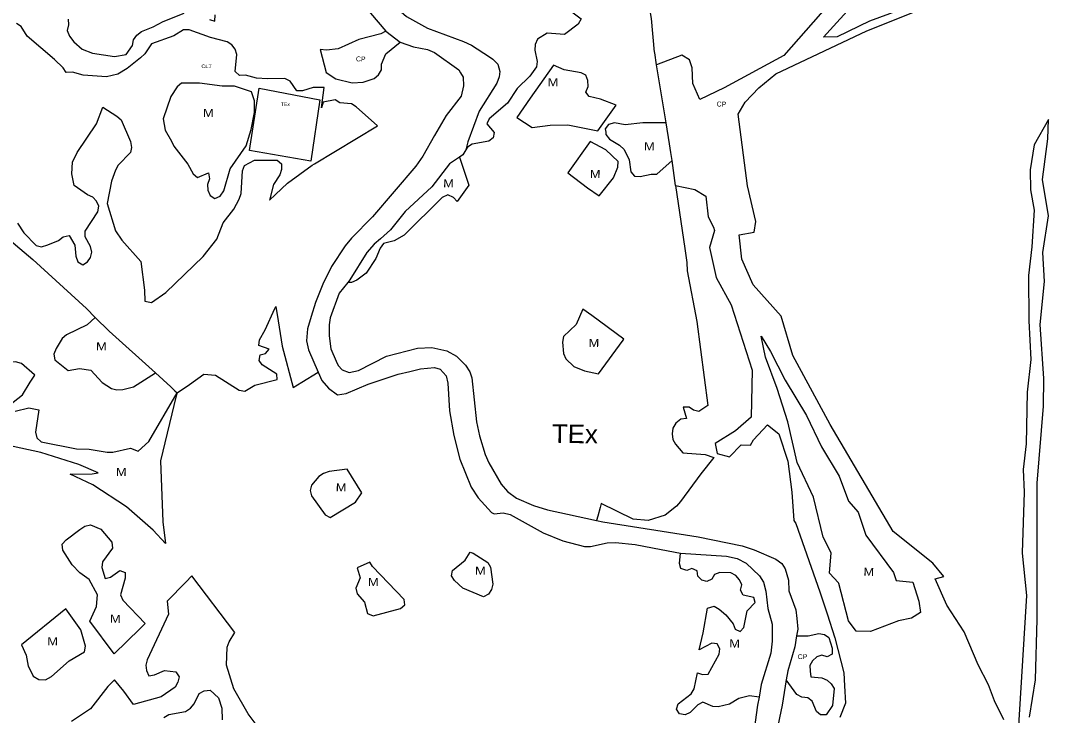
# Model space of a CAD drawing. Extents: x 713589 to 726391, y 7177764 to 7191819.
# Drawn here: x 717458 to 718794, y 7180202 to 7181104 of the extents above; entities that cross this region are included whole.
import ezdxf
from ezdxf.enums import TextEntityAlignment as Align

# ---------------------------------------------------------------- set-up
doc = ezdxf.new("R2010")
doc.units = 0
doc.header["$LTSCALE"] = 2.6
doc.layers.add('63', color=7, linetype='Continuous', lineweight=25)

msp = doc.modelspace()

# ---------------------------------------------------------------- linework, layer by layer
at = {"layer": '63'}
for p, q in [((717932.94, 7181090.31), (717951.45, 7181076.06)), ((718297.19, 7180971.48), (718284.8, 7181046.78)), ((718309.5, 7180890.28), (718304.79, 7180922.77))]:
    msp.add_line(p, q, dxfattribs=at)
for points in [[(717975.51, 7181305.21), (717968.19, 7181295.97), (717951.58, 7181282.26), (717926.69, 7181264.78), (717912.02, 7181249.6), (717905.6, 7181239.24), (717896.88, 7181208.26), (717896.73, 7181192.35), (717901.18, 7181177.19), (717910.76, 7181162.32), (717935.07, 7181131.68), (717959.73, 7181109.56), (717987.25, 7181094.37), (718033.83, 7181076.88), (718044.38, 7181072.47), (718067.72, 7181057.05), (718072.15, 7181054.12), (718078.47, 7181047.53), (718081.11, 7181038.35), (718080.28, 7181031.2), (718077.14, 7181023.14), (718054.19, 7180986.8), (718039.34, 7180946.76), (718036.99, 7180936.65)], [(718284.8, 7181046.78), (718282.27, 7181062.19), (718282.17, 7181063.2), (718278.04, 7181106.99), (718270.15, 7181153.06), (718266.4, 7181200.41)], [(717890.61, 7181140.52), (717932.94, 7181090.31)], [(718526.07, 7181145.73), (718450.04, 7181058.87), (718372.71, 7181016.76), (718340.78, 7181001.63), (718331.9, 7181022.36), (718330.92, 7181042.76), (718327.3, 7181053.3), (718317.43, 7181059.55), (718284.8, 7181046.78)], [(718600.11, 7181117.75), (718561.28, 7181103.6), (718519.48, 7181083.21), (718501.71, 7181082.88), (718545.49, 7181130.59)], [(717520.19, 7181106.21), (717520.84, 7181098.64), (717519.2, 7181091.4), (717522.16, 7181083.83), (717527.75, 7181076.59), (717538.61, 7181067.04), (717552.1, 7181061.78), (717580.73, 7181057.49), (717595.54, 7181060.12), (717603.77, 7181071.97), (717605.41, 7181079.21), (717609.36, 7181085.46), (717615.62, 7181090.06), (717630.75, 7181095.98), (717643.59, 7181103.22), (717670.9, 7181113.75)], [(717703.81, 7181105.51), (717710.72, 7181103.54), (717711.38, 7181111.77)], [(718171.33, 7181122.3), (718174.6, 7181115.78), (718186.78, 7181106.57), (718182.83, 7181099.66), (718165.05, 7181086.17), (718142.68, 7181087.82), (718130.17, 7181080.25), (718127.21, 7181073.34), (718126.55, 7181065.77), (718129.51, 7181051.29), (718128.85, 7181044.05), (718119.96, 7181031.88), (718103.5, 7181016.09), (718091, 7180997), (718067.3, 7180976.6), (718064.01, 7180970.02), (718073.88, 7180958.83), (718072.23, 7180951.92), (718066.64, 7180947.65), (718045.25, 7180943.7), (718038.99, 7180940.08), (718036.99, 7180936.65)], [(718735.81, 7180196.62), (718723.68, 7180221.01), (718716.12, 7180242.07), (718702.63, 7180267.74), (718684.21, 7180310.85), (718661.84, 7180345.08), (718646.42, 7180379.46), (718657.76, 7180382.5), (718643.42, 7180399.71), (718592.09, 7180440.85), (718510.18, 7180579.73), (718461.82, 7180669.25), (718446.69, 7180720.58), (718410.17, 7180761.07), (718395.37, 7180794.63), (718392.09, 7180826.23), (718411.5, 7180829.51), (718413.48, 7180843.33), (718402.96, 7180889.73), (718390.8, 7180982.86), (718399.69, 7180998.33), (718417.46, 7181017.08), (718439.51, 7181035.18), (718557.66, 7181090.77), (718617.55, 7181114.78)], [(717539.92, 7181033.48), (717526.1, 7181037.1), (717517.87, 7181036.77), (717513.92, 7181042.7), (717502.41, 7181053.89), (717467.2, 7181083.84), (717459.31, 7181096.67), (717453.39, 7181100.62)], [(717462.88, 7180828.48), (717478.67, 7180812.35), (717485.91, 7180810.71), (717493.81, 7180813.01), (717507.63, 7180818.6), (717513.89, 7180823.53), (717521.45, 7180825.18), (717529.02, 7180812.67), (717530.33, 7180798.19), (717532.97, 7180790.95), (717539.55, 7180787), (717545.47, 7180790.95), (717549.42, 7180796.87), (717551.07, 7180803.78), (717549.42, 7180811.02), (717542.51, 7180823.53), (717542.52, 7180830.77), (717558.97, 7180856.1), (717559.96, 7180863.34), (717557.33, 7180869.93), (717552.4, 7180875.19), (717545.49, 7180878.16), (717528.05, 7180890.33), (717525.09, 7180905.14), (717525.75, 7180920.28), (717532, 7180933.11), (717557.35, 7180970.29), (717565.25, 7180992.01), (717583.35, 7180980.16), (717589.27, 7180975.22), (717601.11, 7180947.25), (717602.76, 7180939.68), (717601.11, 7180932.77), (717585.31, 7180916.32), (717581.69, 7180910.07), (717576.42, 7180895.59), (717570.82, 7180866.96), (717582, 7180831.42), (717590.23, 7180819.24), (717614.58, 7180791.27), (717619.51, 7180754.41), (717619.83, 7180739.93), (717628.39, 7180738.29), (717647.15, 7180751.12), (717695.53, 7180797.84), (717713.3, 7180820.54), (717721.86, 7180841.6), (717735.36, 7180859.36), (717742.6, 7180872.53), (717744.9, 7180879.77), (717746.88, 7180909.38), (717749.52, 7180915.96), (717762.35, 7180923.2), (717791.97, 7180923.19), (717797.56, 7180918.26), (717797.56, 7180911.02), (717795.25, 7180903.78), (717787.03, 7180891.28), (717781.76, 7180871.2), (717805.45, 7180893.25), (717837.38, 7180916.6), (717840.45, 7180918.45), (717922.16, 7180967.72), (717894.65, 7180992.28), (717888.4, 7180996.23), (717873.26, 7180997.55), (717867.34, 7181001.5), (717851.54, 7180998.21), (717849.65, 7180990.81), (717853.05, 7181017.48), (717838.71, 7181017.3), (717824.56, 7181013.02), (717817.32, 7181013.03), (717808.77, 7181025.53), (717801.86, 7181029.15), (717779.48, 7181028.5), (717765, 7181029.49), (717750.52, 7181033.44), (717742.96, 7181033.11), (717737.36, 7181038.05), (717739.34, 7181060.1), (717737.37, 7181067.34), (717733.09, 7181072.93), (717726.84, 7181076.55), (717705.12, 7181082.15), (717677.48, 7181092.03), (717670.24, 7181092.03), (717657.41, 7181084.46), (717628.78, 7181073.94), (717619.89, 7181061.11), (717614.29, 7181055.84), (717596.85, 7181042.02), (717584.67, 7181034.79), (717570.19, 7181031.17), (717539.92, 7181033.48)], [(717932.94, 7181090.31), (717926.59, 7181087.05), (717897.96, 7181079.81), (717870.97, 7181067.64), (717855.83, 7181065.67), (717847.84, 7181066.72), (717855.53, 7181036.99), (717868, 7181028.81), (717889.39, 7181023.54), (717903.54, 7181024.2), (717917.69, 7181029.13), (717923.29, 7181033.74), (717927.24, 7181040.32), (717927.24, 7181047.56), (717932.83, 7181061.05), (717951.45, 7181076.06)], [(717951.45, 7181076.06), (717968.79, 7181069.97), (717987.3, 7181066.57), (717996.39, 7181062.82), (718027.75, 7181040.48), (718030.13, 7181036.45), (718033.48, 7181030.78), (718033.95, 7181019.44), (718030.76, 7181005.99), (718011.29, 7180981.19), (717996.42, 7180955.23), (717981.2, 7180928.22), (717972.12, 7180915.44), (717915.68, 7180849.6), (717888.61, 7180821.73), (717880.26, 7180811.89), (717862.62, 7180784.98), (717851.28, 7180762.04), (717841.73, 7180738.09), (717836.18, 7180720), (717831.31, 7180704.15), (717830.16, 7180688.3), (717832.63, 7180676.81), (717845.15, 7180647.79)], [(718297.19, 7180971.48), (718267.04, 7180971.3), (718244.01, 7180968.68), (718229.86, 7180971.31), (718222.29, 7180969.34), (718218.01, 7180963.74), (718218.62, 7180959.26), (718219, 7180956.5), (718223.6, 7180950.25), (718236.77, 7180942.35), (718242.69, 7180936.76), (718249.27, 7180923.59), (718251.24, 7180907.8), (718255.84, 7180902.2), (718263.41, 7180901.87), (718277.89, 7180904.83), (718285.13, 7180904.83), (718304.79, 7180922.77)], [(718304.79, 7180922.77), (718303.31, 7180933.11), (718301.7, 7180944.09), (718297.19, 7180971.48)], [(718788.5, 7180765.41), (718786.53, 7180803.25), (718793.78, 7180850.64), (718786.22, 7180898.03), (718793.14, 7180950.68), (718793.75, 7180975.61), (718775.04, 7180942.78), (718770.09, 7180910.53), (718770.42, 7180884.54), (718775.02, 7180858.21), (718772.38, 7180810.5), (718767.77, 7180773.31), (718768.41, 7180714.41), (718771.04, 7180664.06), (718766.09, 7180621.61), (718764.77, 7180554.81), (718761.14, 7180521.57), (718762.12, 7180491.96), (718759.82, 7180413.44), (718759.81, 7180412.98), (718765.06, 7180358.02), (718753.62, 7180167.91)], [(718036.99, 7180936.65), (718033.14, 7180929.96), (718028.78, 7180927.07)], [(718028.78, 7180927.07), (718029.74, 7180924.17), (718040.9, 7180890.42), (718025.47, 7180869.45), (718020.88, 7180874.6), (718013.64, 7180877.89), (718006.4, 7180874.6), (717956.71, 7180825.58), (717943.87, 7180818.34), (717930.05, 7180814.73), (717925.44, 7180808.8), (717919.84, 7180795.31), (717907.34, 7180776.23), (717895.16, 7180767.35), (717888.25, 7180764.39), (717883.49, 7180764.34)], [(718028.78, 7180927.07), (718015.63, 7180918.38), (717992.77, 7180888.31), (717958.24, 7180856.36), (717938.99, 7180832.49), (717926.18, 7180820.78), (717917.72, 7180813.83), (717908.47, 7180803.06), (717886.2, 7180767.77), (717883.49, 7180764.34)], [(718309.5, 7180890.28), (718321.38, 7180808.49), (718324.05, 7180790.09), (718324.53, 7180779.41), (718337.2, 7180713.41), (718351.43, 7180604.53), (718339.72, 7180596.87), (718332.81, 7180598.52), (718326.89, 7180602.47), (718319.32, 7180602.14), (718323.6, 7180587.66), (718316.36, 7180586.68), (718309.78, 7180581.74), (718305.83, 7180575.16), (718304.84, 7180567.59), (718305.82, 7180560.35), (718309.11, 7180554.1), (718318.65, 7180543.24), (718347.94, 7180540.93), (718359.13, 7180536.92), (718342.1, 7180515.97), (718315.7, 7180479.81), (718310.5, 7180473.85), (718296.02, 7180462.34), (718273.65, 7180455.43), (718254.23, 7180456.75), (718212.81, 7180477.47), (718211.46, 7180472.24), (718208.49, 7180460.71), (718206.73, 7180455.32)], [(718309.5, 7180890.28), (718334.51, 7180884.81), (718348.66, 7180876.25), (718351.94, 7180849.27), (718358.78, 7180835.87), (718359.78, 7180831.77), (718353.58, 7180809.78), (718362.13, 7180770.62), (718381.54, 7180735.4), (718408.84, 7180650.5), (718407.51, 7180589.29), (718387.44, 7180571.53), (718361.01, 7180555.13), (718363.5, 7180542.29), (718379.35, 7180537.66), (718394.67, 7180553.43), (718406.52, 7180553.09), (718410.8, 7180560), (718428.9, 7180579.42), (718443.38, 7180567.9), (718455.22, 7180532.35), (718460.47, 7180491.88), (718463.15, 7180455.39), (718465.73, 7180451.4), (718496.6, 7180362.73), (718506.52, 7180334.24), (718516.38, 7180302.98), (718527.89, 7180257.57), (718528.87, 7180240.76), (718530.19, 7180218.08), (718522.62, 7180199.65)], [(717431.49, 7180829.8), (717474.59, 7180794.25), (717544.01, 7180730.4), (717555.57, 7180718.96)], [(717454.33, 7180841.32), (717462.88, 7180828.48)], [(717883.49, 7180764.34), (717872.51, 7180750.43), (717860.82, 7180718.26), (717859.23, 7180709.27), (717859.59, 7180694.87), (717861.62, 7180678.14), (717868.67, 7180661.99), (717871.04, 7180656.56), (717876.36, 7180650.69), (717885.32, 7180647.18), (717897.49, 7180649.75), (717933.99, 7180668.55), (717974.1, 7180678.91), (717992.98, 7180679.69), (718012.4, 7180675.35), (718024.74, 7180668.76), (718036.55, 7180657.03), (718042.01, 7180648.36), (718044.77, 7180640.52), (718050.69, 7180583.16), (718054.85, 7180565.16), (718061.99, 7180541.01), (718066.84, 7180529.99), (718082.68, 7180502.17), (718091.01, 7180493.06), (718102.88, 7180484.41), (718124.73, 7180474.54), (718142.9, 7180468.88), (718169.17, 7180463.61), (718206.73, 7180455.32)], [(718769.31, 7180199.74), (718776.89, 7180248.44), (718779.21, 7180327.09), (718779.23, 7180425.23), (718779.24, 7180503.8), (718787.48, 7180603.84), (718787.82, 7180639.7), (718783.22, 7180709.8), (718788.5, 7180765.41)], [(717661.8, 7180620.76), (717678.12, 7180631.59), (717696.55, 7180645.08), (717711.69, 7180643.76), (717742.62, 7180624.34), (717749.86, 7180623.02), (717762.69, 7180630.92), (717791.98, 7180638.15), (717791.33, 7180645.39), (717772.57, 7180657.24), (717768.29, 7180662.84), (717769.94, 7180670.08), (717776.85, 7180672.05), (717781.46, 7180677.64), (717767.97, 7180682.58), (717768.96, 7180689.82), (717776.2, 7180702.65), (717788.95, 7180730.25), (717790.22, 7180733), (717790.47, 7180730.52), (717793.27, 7180714.32), (717798.24, 7180681.59), (717812.43, 7180628.05), (717823.97, 7180635.01), (717845.15, 7180647.79)], [(717555.57, 7180718.96), (717545.13, 7180709.14), (717518.14, 7180696.32), (717512.55, 7180691.38), (717504.65, 7180678.55), (717501.68, 7180670.98), (717503, 7180663.74), (717520.48, 7180649.97), (717535.14, 7180652.59), (717549.69, 7180650.34), (717564.6, 7180634.32), (717576.6, 7180626.63), (717583.43, 7180624.94), (717591.17, 7180625.33), (717605.42, 7180628.7), (717633.69, 7180646.71)], [(717555.57, 7180718.96), (717573.62, 7180701.11), (717633.69, 7180646.71)], [(717633.69, 7180646.71), (717653.57, 7180628.7), (717658.9, 7180623.56), (717661.8, 7180620.76)], [(717845.15, 7180647.79), (717849.74, 7180637.14), (717858.46, 7180626.9), (717870.09, 7180618.55), (717881.31, 7180620.09), (717909.94, 7180632.13), (717949.1, 7180645.35), (717964.21, 7180648.68), (717977.9, 7180652.23), (717996.39, 7180654.03), (718003.47, 7180651.73), (718011.42, 7180643.01), (718013.75, 7180633.58), (718015.82, 7180597.41), (718021.23, 7180565.4), (718029.23, 7180534.69), (718043.7, 7180498.44), (718053.08, 7180484.8), (718070.46, 7180465.6), (718073.91, 7180463.98), (718085.23, 7180465.2), (718094.63, 7180463.17), (718137.31, 7180439.19), (718163.03, 7180428.9), (718191.02, 7180421.54), (718195.73, 7180421.5), (718198.88, 7180421.47), (718220.41, 7180426.05), (718231.16, 7180426.58), (718256.82, 7180423.98), (718290.54, 7180417.73), (718315.94, 7180412.89)], [(717451.39, 7180597.08), (717469.16, 7180601.68), (717482.19, 7180599.05), (717478.04, 7180569.76), (717479.68, 7180562.52), (717485.28, 7180557.26), (717531.34, 7180548.36), (717547.47, 7180548.03), (717571.16, 7180543.75), (717578.4, 7180543.75), (717601.11, 7180549.01), (717611.17, 7180545.26), (717625.06, 7180557.96), (717661.8, 7180620.76), (717660.61, 7180617.18), (717640.2, 7180532.61), (717643.15, 7180453.64), (717646.75, 7180425.54), (717630.97, 7180442.78), (717596.09, 7180473.06), (717552.33, 7180501.37), (717522.78, 7180515.24), (717551.35, 7180515.85), (717559.35, 7180517.29), (717534.02, 7180527.91), (717484.66, 7180543.71), (717432.67, 7180554.91)], [(718206.73, 7180455.32), (718214.82, 7180453.53), (718338.71, 7180433.94), (718395.82, 7180422.23), (718411.51, 7180417.25), (718439.72, 7180405.03), (718447.34, 7180399.35), (718451.65, 7180392.37), (718456.2, 7180377.79), (718456.62, 7180363.96), (718465.77, 7180339.2), (718466.83, 7180328.17)], [(718417.78, 7180225.72), (718405.38, 7180227.39), (718391.76, 7180224.09), (718379.46, 7180216.82), (718364.78, 7180213.25), (718357.77, 7180213.65), (718344.81, 7180219.47), (718338.46, 7180216.03), (718328.54, 7180205.98), (718321.66, 7180203.07), (718314.52, 7180204.4), (718310.55, 7180210.22), (718312.8, 7180217.22), (718329.86, 7180230.18), (718333.57, 7180236.66), (718337.8, 7180257.56), (718344.55, 7180255.17), (718351.82, 7180255.7), (718366.11, 7180281.49), (718367.04, 7180288.63), (718363.6, 7180295.11), (718356.46, 7180295.77), (718339.97, 7180287.5), (718345.45, 7180309.4), (718350.73, 7180341.6), (718359.59, 7180343.83), (718366.22, 7180340.16), (718374.79, 7180332.59), (718384.31, 7180320.95), (718386.69, 7180314.07), (718393.31, 7180311.29), (718398.07, 7180316.45), (718402.44, 7180337.87), (718412.89, 7180348.72), (718411.17, 7180355.46), (718397.15, 7180358.37), (718393.71, 7180364.59), (718395.56, 7180371.6), (718392.52, 7180378.08), (718387.76, 7180383.9), (718381.36, 7180387.18), (718366.97, 7180387.66), (718360.04, 7180385.31), (718356.6, 7180379.22), (718350.12, 7180375.92), (718343.38, 7180377.9), (718338.22, 7180382.8), (718337.3, 7180389.94), (718330.69, 7180392.72), (718323.81, 7180390.34), (718316.4, 7180392.85), (718314.42, 7180399.47), (718315.94, 7180412.89)], [(718315.94, 7180412.89), (718375.59, 7180408.9), (718389.43, 7180406.08), (718400.89, 7180399.61), (718418.52, 7180383.35), (718423.46, 7180375.05), (718426.7, 7180363.41), (718429.43, 7180341.05), (718435.04, 7180320.51), (718435.01, 7180298.64), (718433.02, 7180283.01), (718420.63, 7180242.17), (718417.78, 7180225.72)], [(717763.42, 7180192), (717754.23, 7180204.14), (717735.53, 7180236.63), (717726.02, 7180267.48), (717727.01, 7180290.78), (717729.31, 7180297.68), (717736.86, 7180309.62), (717681.19, 7180383.43), (717673.17, 7180375.13), (717648.95, 7180350.45), (717650.55, 7180333.79), (717622.97, 7180274.39), (717621.33, 7180267.5), (717621.98, 7180260.28), (717625.26, 7180253.72), (717632.48, 7180254.7), (717645.61, 7180260.61), (717660.38, 7180258.63), (717664.32, 7180252.4), (717662.67, 7180245.18), (717659.39, 7180238.94), (717641.01, 7180226.48), (717605.05, 7180216.49), (717592.52, 7180233.84), (717580.44, 7180248.56), (717571.77, 7180239.62), (717549.45, 7180210.74), (717524.83, 7180194.33)], [(718466.83, 7180328.17), (718468.17, 7180314.29), (718466.66, 7180305.49)], [(718466.66, 7180305.49), (718481.5, 7180305.42), (718495.65, 7180308.38), (718502.89, 7180307.39), (718508.49, 7180303.11), (718512.76, 7180289.29), (718512.76, 7180281.72), (718506.51, 7180278.11), (718499.6, 7180280.41), (718492.69, 7180278.11), (718487.42, 7180273.17), (718483.8, 7180266.92), (718484.13, 7180259.68), (718485.11, 7180252.44), (718499.59, 7180250.79), (718506.17, 7180247.83), (718511.44, 7180243.22), (718515.38, 7180236.97), (718513.41, 7180215.25), (718505.18, 7180203.08), (718497.61, 7180202.75), (718492.34, 7180207.36), (718486.75, 7180220.52), (718481.16, 7180225.13), (718473.26, 7180225.79), (718467.01, 7180229.41), (718453.27, 7180248.52)], [(718466.66, 7180305.49), (718464.19, 7180291.05), (718455.25, 7180260.24), (718453.27, 7180248.52)], [(718453.27, 7180248.52), (718447.7, 7180215.62), (718440.47, 7180180.39)], [(717644.62, 7180199.56), (717651.18, 7180203.17), (717672.84, 7180207.11), (717679.08, 7180211.37), (717684, 7180217.28), (717690.57, 7180230.41), (717696.8, 7180234.01), (717704.68, 7180235), (717715.51, 7180224.82), (717719.77, 7180211.37), (717720.43, 7180196.6)], [(718417.78, 7180225.72), (718416.02, 7180215.6), (718411.5, 7180183.76), (718414.1, 7180158.63), (718430.81, 7180094.32), (718451.52, 7180039.92), (718460.36, 7180018.74), (718474.48, 7179994.61), (718481.19, 7179977.94), (718482.95, 7179964.54), (718477.85, 7179941.62), (718478, 7179926.8), (718483.38, 7179909.83), (718495.38, 7179892.46), (718501.65, 7179886), (718510.02, 7179881), (718546.1, 7179876.34), (718573.47, 7179863.35)]]:
    msp.add_lwpolyline(points, dxfattribs=at)
for points in [[(718193.01, 7181011.46), (718195.64, 7181018.7), (718195.32, 7181026.27), (718193.01, 7181033.18), (718186.76, 7181036.47), (718164.72, 7181040.1), (718150.86, 7181046.16), (718120.39, 7181003.69), (718102.98, 7180978.4), (718122.91, 7180965.41), (718146.28, 7180968.36), (718169.31, 7180968.69), (718208.3, 7180961.23), (718232.06, 7180994.61), (718211.77, 7181002.25), (718197.29, 7181005.87)], [(717736.37, 7181019.29), (717720.25, 7181018.97), (717690.96, 7181022.92), (717667.6, 7181022.92), (717662, 7181018.32), (717653.77, 7181005.49), (717643.9, 7180976.86), (717646.53, 7180962.05), (717654.7, 7180947.49), (717657.71, 7180940.99), (717675.8, 7180917.95), (717682.71, 7180905.11), (717688.31, 7180900.51), (717702.46, 7180906.43), (717703.77, 7180898.86), (717701.47, 7180891.62), (717701.8, 7180884.05), (717704.76, 7180877.14), (717711.01, 7180873.19), (717717.92, 7180876.48), (717722.53, 7180883.06), (717730.76, 7180911.69), (717751.5, 7180941.63), (717758.08, 7180963.02), (717762.36, 7180985.06), (717762.36, 7180999.87), (717758.42, 7181011.72)], [(717835.4, 7180921.54), (717755.77, 7180935.38), (717768.62, 7181016.33), (717847.45, 7181001.21)], [(718198.29, 7180947.17), (718169.53, 7180906.77), (718195.07, 7180887.18), (718210.07, 7180876.78), (718228.86, 7180899.9), (718234.46, 7180913.72), (718234.79, 7180921.29), (718218.67, 7180936.43)], [(718177.15, 7180655.08), (718190.97, 7180649.49), (718209.24, 7180645.48), (718241.11, 7180689.4), (718241.98, 7180690.7), (718200.64, 7180721.33), (718189.06, 7180729.51), (718180.12, 7180709.71), (718163.67, 7180693.92), (718162.35, 7180686.68), (718163.99, 7180671.87), (718166.95, 7180664.96)], [(718455.23, 7180583.36), (718441.41, 7180626.8), (718426.28, 7180667.28), (718420.69, 7180694.59), (718432.87, 7180674.52), (718451.94, 7180637.33), (718479.58, 7180591.58), (718498.99, 7180550.77), (718522.01, 7180512.6), (718534.18, 7180480.35), (718546.69, 7180465.87), (718556.55, 7180436.25), (718592.41, 7180387.87), (718595.84, 7180377.2), (718617.55, 7180375.05), (718625.31, 7180350.68), (718627.62, 7180335.87), (718615.77, 7180328.63), (718598.98, 7180325.01), (718562.78, 7180311.2), (718544.03, 7180311.53), (718534.16, 7180325.03), (718521.3, 7180373.25), (718521, 7180374.39), (718509.16, 7180386.9), (718511.47, 7180413.22), (718501.27, 7180433.63), (718488.77, 7180485.62), (718467.39, 7180530.71)], [(717405.59, 7180638.75), (717417.95, 7180626.64), (717421.38, 7180623.28), (717429.93, 7180602.22), (717436.84, 7180599.25), (717460.87, 7180618.34), (717471.07, 7180634.65), (717476.92, 7180644.01), (717476.67, 7180644.33), (717459.56, 7180659.14), (717451.99, 7180661.12), (717444.42, 7180660.79), (717414.15, 7180656.85), (717407.9, 7180653.23), (717404.93, 7180645.99)], [(717836.56, 7180487.38), (717854.32, 7180462.7), (717860.9, 7180459.08), (717893.48, 7180478.81), (717901.64, 7180491.08), (717882.65, 7180521.85), (717859.6, 7180518.64), (717852.03, 7180516.34), (717845.77, 7180512.39), (717836.23, 7180501.2), (717834.58, 7180494.29)], [(717577.74, 7180419.37), (717564.91, 7180401.61), (717564.25, 7180394.04), (717568.52, 7180379.89), (717575.43, 7180381.53), (717587.28, 7180390.09), (717594.19, 7180387.78), (717594.52, 7180380.54), (717588.26, 7180358.82), (717591.22, 7180351.58), (717620.41, 7180321.36), (717613.57, 7180314.38), (717580.1, 7180282.25), (717548.49, 7180324.61), (717557, 7180343.69), (717558.65, 7180358.5), (717547.46, 7180378.57), (717535.62, 7180387.13), (717525.42, 7180397.66), (717513.57, 7180416.75), (717512.59, 7180424.32), (717517.85, 7180430.24), (717535.63, 7180443.4), (717541.88, 7180447.68), (717549.45, 7180449.65), (717562.61, 7180444.06), (717577.09, 7180426.94)], [(718059.97, 7180356.04), (718032.99, 7180367.24), (718022.13, 7180377.11), (718018.18, 7180383.36), (718019.5, 7180390.27), (718035.96, 7180403.76), (718042.52, 7180413.97), (718046.49, 7180412.64), (718065.57, 7180400.79), (718068.86, 7180394.54), (718071.82, 7180372.49), (718070.17, 7180365.58), (718066.22, 7180359.66)], [(717916.49, 7180331.39), (717952.03, 7180340.92), (717957.63, 7180345.53), (717956.64, 7180352.77), (717915.52, 7180395.56), (717912.37, 7180401.28), (717895.73, 7180393.78), (717899.72, 7180380.75), (717894.12, 7180367.26), (717895.77, 7180360.02), (717905.31, 7180349.16), (717909.25, 7180334.35)], [(717498.74, 7180252.55), (717521.77, 7180272.95), (717541.52, 7180284.79), (717542.84, 7180292.03), (717536.92, 7180313.09), (717517.38, 7180340.69), (717459.83, 7180293.67), (717465.83, 7180280.2), (717468.46, 7180266.05), (717471.75, 7180259.46), (717475.04, 7180253.21), (717482.28, 7180248.93), (717490.84, 7180248.27)]]:
    msp.add_lwpolyline(points, close=True, dxfattribs=at)

# ---------------------------------------------------------------- texts
for s, height, width, p in [('CP', 6.4, 1.05, (717900.39, 7181051.21)), ('CLT', 4.64, 1.15, (717700.12, 7181042.54)), ('M', 10.4, 1.2, (718150.12, 7181018.99)), ('M', 10.4, 1.2, (717702.38, 7180979.06)), ('TEx', 4.8, 1.05, (717802.4, 7180993.37)), ('CP', 6.4, 1.05, (718369.02, 7180992.65)), ('M', 10.4, 1.2, (718275.23, 7180935.86)), ('M', 10.4, 1.2, (718204.92, 7180899.94)), ('M', 10.4, 1.2, (718014.31, 7180887.82)), ('M', 10.4, 1.2, (717563.43, 7180676.18)), ('M', 10.4, 1.2, (718203.24, 7180680.52)), ('TEx', 24, 1.05, (718178.45, 7180555.71)), ('M', 10.4, 1.2, (717589.26, 7180513.02)), ('M', 10.4, 1.2, (717874.83, 7180492.96)), ('M', 10.4, 1.2, (718055.76, 7180384.91)), ('M', 10.4, 1.2, (718560.36, 7180383.42)), ('M', 10.4, 1.2, (717916.7, 7180370.08)), ('M', 10.4, 1.2, (717581.56, 7180322.39)), ('M', 10.4, 1.2, (717500.08, 7180293.17)), ('M', 10.4, 1.2, (718386.02, 7180290.29)), ('CP', 6.4, 1.05, (718474.27, 7180275.26))]:
    msp.add_text(s, height=height, rotation=359.062, dxfattribs=dict(at, width=width)).set_placement(p, align=Align.CENTER)

doc.saveas('drawing.dxf')
